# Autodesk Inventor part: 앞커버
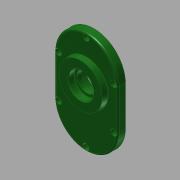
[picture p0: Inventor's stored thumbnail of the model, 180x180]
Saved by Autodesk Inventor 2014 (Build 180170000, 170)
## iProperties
Created: 2016-12
Part Number: 앞커버
Material: Aluminum 6061
Document SubType Name: Modeling
Designer: mduedu
Density: 2.71 g/cm^3
Appearance: Smooth - Dark Forest Green
Mass: 264.838 g
Surface Area: 264.105 cm^2
Volume: 97.726 cm^3
Author: mduedu
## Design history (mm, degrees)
sketch "스케치1"
  geometry: L1 (40, -25)-(40, 25); L2 (-40, 25)-(-40, -25); L3 (-40, -25)-(40, 25); L4 (40, -25)-(-40, 25); A1 r 40 centre (0, 25) between (40, 25) and (-40, 25); A2 r 40 centre (0, -25) between (-40, -25) and (40, -25); 1 further point
  constraints: 8 end point, 4 point on circle, 4 tangent, 2 centre point, 2 midpoint, 1 parallel, 1 vertical
  dimensions: "d0" = 130 dimension on A2 A1; "d2" = 80 distance between parallel lines of L1 L2
extrude "돌출1" new body sketch "스케치1" distance "d3" = 10; taper "d4" = 0 deg
sketch "스케치2"
  geometry: C1 r 21 at (0, 11); 1 further point
  constraints: 1 centre point, 1 vertical alignment
  dimensions: "d5" = 42 diameter of C1; "d7" = 11 distance of C1.centre point (0, 0)
extrude "돌출2" join sketch "스케치2" distance "d8" = 7; taper "d9" = 0 deg
sketch "스케치3"
  geometry: C1 r 15 at (0, -33.1); C2 r 21 at (0, 11) reference; 1 further point
  constraints: 1 centre point, 1 vertical alignment
  dimensions: "d10" = 30 diameter of C1; "d71" = 44.1 distance of C1.centre C2.centre
extrude "돌출3" join sketch "스케치3" distance "d12" = 7; taper "d13" = 0 deg
sketch "스케치4"
  geometry: C1 r 28 at (0, 11); A1 r 21 centre (0, 11) between (8.978, -7.984) and (-8.978, -7.984) reference; 1 further point
  constraints: 1 centre point, 1 coincident
  dimensions: "d14" = 56 diameter of C1
extrude "돌출4" join sketch "스케치4" distance "d15" = 7; taper "d16" = -5 deg
hole "구멍1" diameter "d19" = 35; stored, may be unused: countersink angle "d23" = 90 deg, drill point angle "d25" = 0 deg; dims "d17" = 10, "d18" = 10, "d20" = 6, "d21" = 4, "d22" = 2, "d24" = 10
hole "구멍2" diameter "d28" = 22; stored, may be unused: countersink angle "d32" = 90 deg, drill point angle "d34" = 0 deg; dims "d26" = 10, "d27" = 10, "d29" = 6, "d30" = 4, "d31" = 2, "d33" = 7
hole "구멍3" diameter "d37" = 19; stored, may be unused: countersink angle "d41" = 90 deg, drill point angle "d43" = 0 deg; dims "d35" = 10, "d36" = 10, "d38" = 6, "d39" = 4, "d40" = 2, "d42" = 1
hole "구멍4" diameter "d46" = 32; stored, may be unused: countersink angle "d50" = 90 deg, drill point angle "d52" = 0 deg; dims "d44" = 10, "d45" = 10, "d47" = 6, "d48" = 4, "d49" = 2, "d51" = 8
hole "구멍5" diameter "d55" = 25; stored, may be unused: countersink angle "d59" = 90 deg, drill point angle "d61" = 0 deg; dims "d53" = 10, "d54" = 10, "d56" = 6, "d57" = 4, "d58" = 2, "d60" = 8
fillet "모깎기1" dims "d62" = 0.3
fillet "모깎기2" dims "d63" = 2
chamfer "모따기1" distance "d64" = 1; stored, may be unused: second distance "d65" = 2, angle "d66" = 45 deg
fillet "모깎기4" dims "d68" = 2
fillet "모깎기5" dims "d69" = 0.3
fillet "모깎기6" dims "d70" = 2
sketch "스케치5"
  geometry: L1 (-40, 25)-(-40, -25) reference; L2 (40, -25)-(40, 25) reference; L3 (35, 25)-(35, -25); L4 (-35, -25)-(-35, 25); A1 r 40 centre (0, 25) between (40, 25) and (-40, 25) reference; A2 r 40 centre (0, -25) between (-40, -25) and (40, -25) reference; A3 r 35 centre (0, 25) between (35, 25) and (-35, 25); A4 r 35 centre (0, -25) between (-35, -25) and (35, -25); 2 further points
  constraints: 5 point on circle, 4 end point, 2 centre point, 1 vertical alignment, 3 other
  dimensions: "d72" = 5 distance between parallel lines of L2 L3
sketch "스케치7"
  geometry: 1 further point
hole "구멍7" sketch "스케치7" at (0, 60) diameter "d80" = 4.5; stored, may be unused: countersink angle "d84" = 90 deg, drill point angle "d86" = 0 deg; dims "d81" = 6, "d82" = 8, "d83" = 4.6, "d85" = 8
node "솔리드1"
pattern_linear "직사각형 패턴1"
